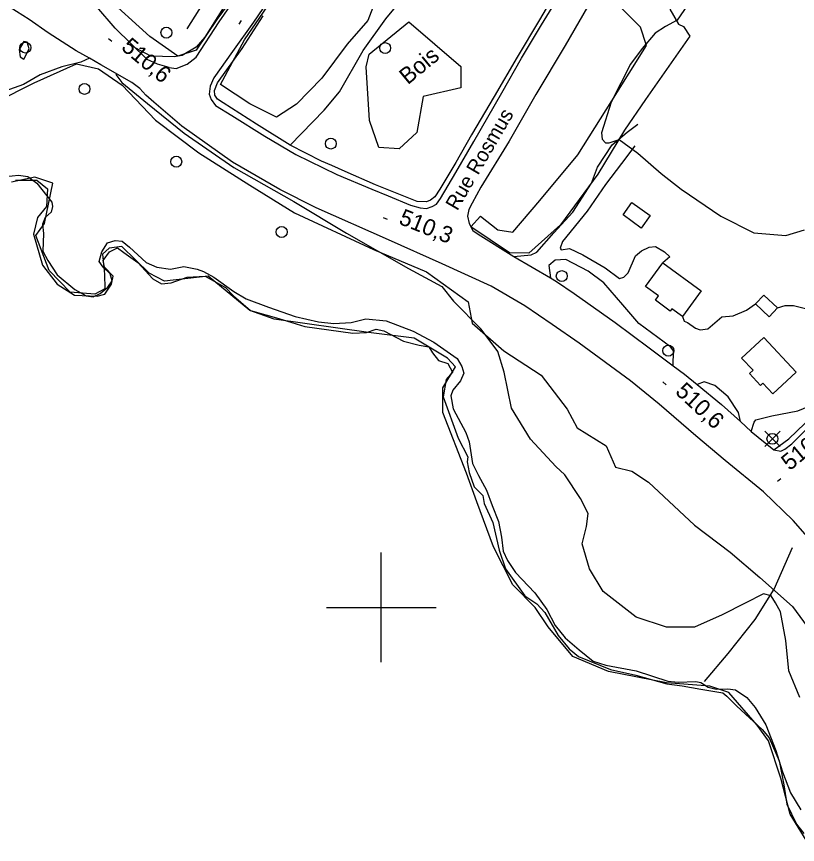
# Model space of a CAD drawing. Extents: x 347059 to 352153, y 6073752 to 6078601.
# Drawn here: x 348500 to 348714.1, y 6075235 to 6075461.9 of the extents above; entities that cross this region are included whole.
import ezdxf

# ---------------------------------------------------------------- set-up
doc = ezdxf.new("R2010")
doc.units = 0
for name, color, linetype in [('Level 1', 7, 'Continuous'), ('Level 19', 7, 'Continuous'), ('Level 2', 7, 'Continuous'), ('Level 21', 7, 'Continuous'), ('Level 22', 7, 'Continuous'), ('Level 3', 7, 'Continuous'), ('Level 31', 7, 'Continuous'), ('Level 36', 7, 'Continuous'), ('Level 4', 7, 'Continuous'), ('Level 44', 7, 'Continuous'), ('Level 61', 7, 'Continuous')]:
    doc.layers.add(name, color=color, linetype=linetype)

msp = doc.modelspace()

# ---------------------------------------------------------------- linework, layer by layer
at = {"layer": 'Level 1'}
for points in [[(348586.89, 6075523.19), (348588.74, 6075526.22), (348589.72, 6075528.31), (348591.57, 6075530.52), (348595.8, 6075537.93), (348597.8, 6075542.22), (348601.17, 6075545.77), (348611.35, 6075553.01), (348622.93, 6075562.08), (348621.01, 6075559.51), (348614.27, 6075550.4), (348605.23, 6075539.9), (348598, 6075529.85), (348588.42, 6075514.02), (348577.01, 6075496.6), (348565.29, 6075478.17), (348558.76, 6075467.65), (348551.57, 6075456.28), (348549.21, 6075453.5), (348545.43, 6075451.26), (348543.17, 6075450.9), (348536.78, 6075451.08), (348532.66, 6075453.22)], [(348527.42, 6075446.27), (348527.22, 6075446.01), (348528.9, 6075443.8), (348535.93, 6075438.06), (348545.95, 6075429.99), (348559.54, 6075420.52), (348576.02, 6075411.19), (348590.44, 6075402.54), (348607.48, 6075392.91), (348616.57, 6075387.96), (348619.81, 6075383.95)], [(348714.74, 6075275.31), (348711.69, 6075282.58), (348711.69, 6075282.58), (348710.87, 6075290.94), (348709.42, 6075298.78), (348708.11, 6075301.22), (348706.88, 6075303.16), (348704.8, 6075303.72), (348699.79, 6075301.14), (348693.41, 6075297.97), (348685.86, 6075294.61), (348678.18, 6075294.61), (348669.87, 6075297.28), (348660.81, 6075304.39), (348657.03, 6075310.57), (348655.05, 6075317.45), (348656.21, 6075322.14), (348656.68, 6075325.73), (348654.6, 6075329.85), (348650.27, 6075336.37), (348647.86, 6075338.64), (348640.86, 6075346.14), (348635.7, 6075354.64), (348633.69, 6075364.43), (348631.9, 6075370.13), (348627.38, 6075376.24), (348619.81, 6075383.95)]]:
    msp.add_lwpolyline(points, dxfattribs=at)
at = {"layer": 'Level 19'}
for points in [[(348501.98, 6075450.24), (348503.48, 6075453.06), (348502.91, 6075454.92), (348502.02, 6075455.08), (348500.67, 6075452.91), (348500.97, 6075450.83), (348501.98, 6075450.24)], [(348519.99, 6075450.5), (348517.58, 6075449.42), (348512.45, 6075448.17), (348506.45, 6075445.97), (348501.92, 6075443.27), (348498.1, 6075441.9), (348493.28, 6075441.36), (348488.71, 6075442.6), (348484.26, 6075443.88), (348476.57, 6075447.79), (348471.59, 6075449.89), (348468.05, 6075450.79), (348463.98, 6075451.17), (348456.84, 6075449.61), (348454.27, 6075450.26)], [(348636.37, 6075396.13), (348641.1, 6075396.6), (348642.61, 6075397.32), (348647.34, 6075402.67), (348652.55, 6075408.27), (348657.58, 6075416.26), (348659.26, 6075420.66), (348663.32, 6075426.73), (348667.39, 6075430.25), (348670.31, 6075432.44)], [(348669.5, 6075426.44), (348665.81, 6075421.66), (348661.45, 6075415.86), (348656.45, 6075408.57), (348649.67, 6075400.25), (348649, 6075398.42), (348649.33, 6075397.94), (348651.63, 6075398.34), (348655.25, 6075396.61), (348661.33, 6075393.01), (348665.34, 6075390.09), (348666.45, 6075390.48), (348667.67, 6075391.72), (348669.71, 6075396.34), (348671.35, 6075397.7), (348673.42, 6075398.74), (348675.2, 6075398.87), (348677.62, 6075397.41), (348679.1, 6075396.08), (348677.18, 6075394.43)], [(348680.05, 6075366.2), (348680.06, 6075370.35), (348679.3, 6075371.44), (348670.6, 6075377.84), (348666.22, 6075382.92), (348660.98, 6075388.95), (348656.75, 6075392.13), (348650.55, 6075395.34), (348647.65, 6075395.11), (348645.91, 6075393.67), (348646.36, 6075390.27)], [(348682.59, 6075379.68), (348683.07, 6075378.46), (348683.92, 6075378.07), (348686.16, 6075376.55), (348687.4, 6075376.07), (348689.48, 6075376.36), (348693.4, 6075379.61), (348696.47, 6075379.91), (348700.16, 6075381.45), (348702.62, 6075383.16)], [(348708.62, 6075382.07), (348710.74, 6075382.77), (348713.04, 6075382.72), (348717.06, 6075381.7), (348721.52, 6075379.23), (348725.3, 6075375.59), (348728.78, 6075371.41), (348732.03, 6075367.33), (348734.32, 6075364.05)], [(348698.43, 6075350.91), (348697.93, 6075353.43), (348695.07, 6075357.68), (348691.41, 6075360.81), (348688.54, 6075361.81), (348686.59, 6075361.05)], [(348701.43, 6075348.24), (348702.24, 6075350.79), (348702.71, 6075351.41), (348707.09, 6075352.48), (348714.22, 6075353.87), (348717.26, 6075355.11), (348721.81, 6075355.53)]]:
    msp.add_lwpolyline(points, dxfattribs=at)
at = {"layer": 'Level 2'}
for points in [[(348718.72, 6075506.29), (348718.55, 6075505.87), (348712.32, 6075499.96), (348709.01, 6075498.34), (348705.59, 6075496.93), (348701.92, 6075494.19), (348699.25, 6075491.97), (348696.35, 6075487.77), (348688.71, 6075477.68), (348686.13, 6075471.65), (348684.8, 6075466.19), (348681.14, 6075460.91), (348677.9, 6075459.2)], [(348677.9, 6075459.2), (348675.09, 6075457.32), (348671.5, 6075453.14), (348668.35, 6075448.88), (348663.06, 6075438.41), (348660.39, 6075430.04), (348660.51, 6075428.27), (348661.45, 6075427.32), (348662.51, 6075427.3), (348665.23, 6075428.2), (348670.35, 6075424.49), (348676.69, 6075418.86), (348682.21, 6075414.57), (348693.08, 6075407.21), (348702.12, 6075402.68), (348710.94, 6075401.94), (348716.01, 6075403.44)], [(348495.23, 6075417.92), (348500.54, 6075418.43), (348503.06, 6075418.12)], [(348503.06, 6075418.12), (348505.52, 6075416.28), (348509.71, 6075411.06), (348509.89, 6075409.87), (348509.46, 6075408.31), (348507.86, 6075406.85), (348507.11, 6075405.03), (348507.38, 6075402.44), (348507.23, 6075397.64), (348508.6, 6075395.03), (348511.16, 6075391.13), (348515.96, 6075387.1), (348519.09, 6075385.41), (348521.04, 6075385.15), (348522.95, 6075386.06), (348525, 6075387.76), (348526.25, 6075389.47), (348525.7, 6075391.42), (348523.76, 6075393.28), (348522.65, 6075394.78), (348523.34, 6075397.48), (348524.95, 6075399.89), (348527.05, 6075400.56), (348528.93, 6075400.38), (348530.97, 6075398.72), (348535.54, 6075394.49), (348538.41, 6075393.27), (348542.22, 6075392.68), (348545.86, 6075393.43), (348549.51, 6075392.72), (348551.27, 6075392.04), (348554.04, 6075390.46), (348559.52, 6075386.58), (348562.9, 6075384.58), (348569.1, 6075382.23), (348576.36, 6075379.72), (348582.78, 6075378.23), (348586.97, 6075377.83), (348591.72, 6075378.03), (348595.75, 6075379.1), (348601.29, 6075378.5), (348608.75, 6075375.74), (348614.36, 6075372.66), (348620.79, 6075368.25), (348622.11, 6075366.01), (348622.59, 6075364.15), (348621.75, 6075362.11), (348619.63, 6075359.55), (348619.05, 6075358), (348619.74, 6075354.43), (348623.14, 6075347.92), (348624.06, 6075345.35), (348624.97, 6075339.43), (348626.63, 6075336.14), (348628.88, 6075332.14), (348630.38, 6075327.92), (348632.16, 6075323.52), (348632.93, 6075319.22), (348633.44, 6075315.38), (348634.59, 6075312.87), (348636.83, 6075309.53), (348642.06, 6075304.01), (348645.42, 6075299.46), (348647.63, 6075295.03), (348650.44, 6075291.63)], [(348650.44, 6075291.63), (348654.21, 6075288.36), (348658.07, 6075285.3), (348661.52, 6075284.18), (348669.87, 6075282.59), (348678.54, 6075279.81), (348681.42, 6075279.54), (348686.22, 6075279.67), (348687.63, 6075279.38), (348689.6, 6075278.16), (348691.76, 6075277.61), (348695.03, 6075277.67), (348697.11, 6075277.4), (348700.18, 6075275.29), (348702.47, 6075272.53), (348705.44, 6075267.81), (348708.2, 6075260.78), (348709.98, 6075254.94), (348712.21, 6075249.2), (348715.04, 6075244.5)]]:
    msp.add_lwpolyline(points, dxfattribs=at)
at = {"layer": 'Level 21'}
for points in [[(348601.9, 6075412.8), (348608.04, 6075410.22), (348610.65, 6075409.53), (348612.35, 6075409.29), (348613.97, 6075409.88), (348615.14, 6075410.47), (348616.23, 6075412.05), (348620.39, 6075419.18), (348625.38, 6075427.67), (348633.04, 6075441.01), (348638.45, 6075450.53), (348643.95, 6075459.67), (348651.96, 6075472.77)], [(348541.79, 6075447.93), (348543.74, 6075447.67), (348546.81, 6075448.87), (348549.25, 6075450.74), (348555.5, 6075460.42), (348561.36, 6075468.96)], [(348657.9, 6075467.03), (348650.44, 6075454), (348642.35, 6075440.54), (348635.04, 6075427.79), (348627.32, 6075415.16), (348624.93, 6075410.78), (348623.95, 6075409.07), (348623.66, 6075407.25), (348624.08, 6075405.19), (348625.06, 6075403.3), (348626.57, 6075402.3), (348636.37, 6075396.13), (348646.36, 6075390.27), (348647.99, 6075389.3), (348652.83, 6075386.02), (348664.11, 6075378.08), (348673.42, 6075371.13), (348680.05, 6075366.2), (348683.12, 6075363.91), (348686.59, 6075361.05), (348693.22, 6075355.57), (348698.43, 6075350.91), (348701.43, 6075348.24), (348707.59, 6075343.19), (348709.49, 6075342.81), (348710.66, 6075343.4), (348712.56, 6075344.82), (348720.13, 6075352.3)], [(348535.41, 6075440.39), (348533.79, 6075442.15), (348531.61, 6075443.88), (348523.14, 6075448.72), (348519.99, 6075450.5), (348516.35, 6075452.55), (348508.63, 6075457.49), (348503.43, 6075461.13), (348498.22, 6075464.4)], [(348541.79, 6075447.93), (348538.63, 6075448.84), (348535.83, 6075450.13), (348527.01, 6075458.74), (348521.98, 6075464.56)], [(348568.84, 6075466.13), (348564.93, 6075460.33), (348559.16, 6075452.33), (348554.05, 6075445.08), (348553.09, 6075442.79), (348552.77, 6075440.64), (348553.33, 6075439.15), (348554.5, 6075437.56), (348558.97, 6075434.81), (348568.02, 6075429.17), (348576.6, 6075424.11), (348587.81, 6075418.59), (348597.43, 6075414.62), (348601.9, 6075412.8)], [(348722.14, 6075313.27), (348712.94, 6075323.79), (348704.81, 6075331.65), (348694.28, 6075340.23), (348686.23, 6075347.02), (348676.16, 6075355.68), (348668.28, 6075362.09), (348654.25, 6075372.43), (348646.83, 6075377.55), (348639.36, 6075382.64), (348630.07, 6075388.02), (348616.69, 6075394.15), (348602, 6075400.76), (348582.17, 6075409.5), (348572.22, 6075414.49), (348559.23, 6075422.05), (348545.3, 6075431.84), (348537.61, 6075438.46), (348535.41, 6075440.39)]]:
    msp.add_lwpolyline(points, dxfattribs=at)
at = {"layer": 'Level 22'}
for points in [[(348574.97, 6075426.71), (348584.34, 6075436.28), (348588.51, 6075441.31), (348595.02, 6075452.57), (348601.26, 6075461.27), (348605.29, 6075466.11), (348608.57, 6075471.76), (348613.69, 6075486.97), (348618.83, 6075495.28), (348627.44, 6075507.37), (348638.42, 6075522.78), (348642.66, 6075527.73), (348650.28, 6075534.42), (348657.91, 6075540.82), (348668.12, 6075548.99), (348679.06, 6075557.38), (348686.99, 6075564.77), (348691.64, 6075569.23), (348695.59, 6075571.53), (348704.1, 6075575.43), (348714.18, 6075580.41), (348727.56, 6075583.17), (348738.27, 6075584.32), (348743.55, 6075585.93)], [(348650.14, 6075472.57), (348643.39, 6075461.04), (348637.21, 6075450.82), (348630.93, 6075439.98), (348624.69, 6075429.47), (348620.41, 6075421.94), (348616.02, 6075414.63), (348614.71, 6075412.49), (348613.44, 6075411.58), (348612.37, 6075411.15), (348609.79, 6075411.26), (348598.36, 6075415.77), (348590.06, 6075419.41)], [(348590.06, 6075419.41), (348586.41, 6075421.1), (348583.56, 6075422.27), (348574.97, 6075426.71), (348565.76, 6075432.45), (348556.64, 6075438.26), (348555.05, 6075439.27), (348554.34, 6075440.4), (348554.29, 6075441.64), (348555.06, 6075443.79), (348561.86, 6075453.18), (348567.63, 6075462.09)], [(348707.59, 6075343.19), (348711.76, 6075346.2), (348716.1, 6075350.35), (348721.81, 6075355.53), (348727.43, 6075359.74), (348733.77, 6075363.71), (348734.32, 6075364.05), (348741.33, 6075368.39), (348751.25, 6075374.58), (348758.79, 6075379.02), (348762.93, 6075381.47)], [(348688.63, 6075279.73), (348695.12, 6075287.36), (348702.5, 6075296.64), (348707.73, 6075305.04), (348712.7, 6075316.46)]]:
    msp.add_lwpolyline(points, dxfattribs=at)
at = {"layer": 'Level 3'}
for p, q in [((348561, 6075459.84), (348561.64, 6075460.86)), ((348525.16, 6075455.91), (348526.08, 6075455.14)), ((348600.51, 6075406.85), (348601.63, 6075406.4)), ((348677.2, 6075361.78), (348678.08, 6075360.96)), ((348708.62, 6075334.58), (348709.54, 6075335.35))]:
    msp.add_line(p, q, dxfattribs=at)
at = {"layer": 'Level 31'}
for points in [[(348666.26, 6075407.53), (348668.71, 6075410.98), (348673.74, 6075407.42), (348671.28, 6075403.96), (348666.26, 6075407.53)], [(348677.18, 6075394.43), (348687.73, 6075386.71), (348682.59, 6075379.68), (348679.64, 6075381.84), (348679.19, 6075381.22), (348675.15, 6075384.18), (348676.01, 6075385.36), (348672.45, 6075387.97), (348677.18, 6075394.43)], [(348704.88, 6075385.57), (348708.62, 6075382.07), (348706.36, 6075379.66), (348702.62, 6075383.16), (348704.88, 6075385.57)], [(348704.85, 6075373.99), (348713.73, 6075364.49), (348707.35, 6075358.53), (348704.61, 6075361.46), (348703.93, 6075360.83), (348700.91, 6075364.07), (348701.9, 6075365), (348698.79, 6075368.33), (348704.85, 6075373.99)]]:
    msp.add_lwpolyline(points, dxfattribs=at)
at = {"layer": 'Level 36'}
for p, q in [((348709.33, 6075344.07), (348705.1, 6075348.3)), ((348705.1, 6075344.07), (348709.33, 6075348.3))]:
    msp.add_line(p, q, dxfattribs=at)
for centre in [(348541.08, 6075457.5), (348502.41, 6075453.41), (348601.05, 6075453.27), (348518.62, 6075442.08), (348586.15, 6075427.1), (348543.77, 6075422.14), (348572.67, 6075402.88), (348649.48, 6075390.8), (348678.68, 6075370.36), (348707.22, 6075346.19)]:
    msp.add_circle(centre, 1.5, dxfattribs=at)
at = {"layer": 'Level 4'}
for points in [[(348546.75, 6075458.56), (348553.32, 6075469.05), (348561.6, 6075479.29), (348572.87, 6075494.65), (348579.29, 6075505.23), (348587.72, 6075517.56), (348592.34, 6075526.37), (348593.08, 6075527.79), (348600.5, 6075537.62), (348606.16, 6075544.94)], [(348499.69, 6075417.03), (348505.54, 6075417.07), (348508.49, 6075414.7), (348508.21, 6075409.87), (348505.74, 6075406.85), (348504.62, 6075402.3), (348507.07, 6075393.81), (348511.12, 6075388.58), (348515.86, 6075385.59), (348522.14, 6075385.29), (348524.16, 6075385.84), (348525.98, 6075388.56), (348526.48, 6075390.77), (348524.07, 6075393.22), (348523.75, 6075395.06), (348525.46, 6075397.45), (348527.66, 6075398.52), (348529.43, 6075397.21), (348533.21, 6075394.47), (348537.33, 6075390.06), (348539.71, 6075388.64), (348542.38, 6075388.97), (348546.81, 6075390.54), (348551.69, 6075390.74), (348557.26, 6075387.68), (348559.43, 6075385.34), (348564.13, 6075381.4), (348571.87, 6075379.16), (348579.05, 6075376.97)], [(348579.05, 6075376.97), (348592.19, 6075375.14), (348595.96, 6075375.32), (348598.56, 6075376.28), (348600.67, 6075375.83), (348606.09, 6075372.94), (348610.4, 6075371.85), (348612.99, 6075371.36), (348614.03, 6075369.74), (348615.66, 6075367.69), (348618.21, 6075366.8), (348619.48, 6075364.46), (348617.81, 6075362.47), (348616.95, 6075357.69), (348621.09, 6075346.35), (348623.71, 6075341.29), (348623.54, 6075339.87), (348624.1, 6075337.01), (348625.42, 6075333.06), (348627.79, 6075330.66), (348628.21, 6075328.44), (348630.53, 6075323.28), (348632.3, 6075315.7), (348634.01, 6075310.56), (348639.34, 6075303.14), (348642.6, 6075300.94), (348644.86, 6075298.59), (348648.52, 6075292.28), (348651.48, 6075288.62), (348654.09, 6075286.56), (348662.84, 6075282.95), (348669.75, 6075281.44), (348678.28, 6075279.08), (348682.52, 6075278.52), (348687.56, 6075277.64), (348693.66, 6075276.57), (348694.69, 6075275.69), (348697.44, 6075272.92), (348704.44, 6075266.5), (348706.3, 6075264.27), (348709.06, 6075257.95), (348710.31, 6075251.36), (348711.17, 6075246.05), (348713.84, 6075240.56), (348715.84, 6075238.06)]]:
    msp.add_lwpolyline(points, dxfattribs=at)
at = {"layer": 'Level 44'}
for points in [[(348583.72, 6075445.01), (348576.72, 6075437.86), (348571.22, 6075434.35), (348563.99, 6075437.97), (348555.94, 6075443.31), (348562.51, 6075455.51), (348567.66, 6075463.08), (348578.56, 6075479.47), (348589.72, 6075495.93), (348600.07, 6075512.62), (348602.96, 6075514.57), (348615.81, 6075506), (348618.95, 6075500.79), (348606.98, 6075494.18), (348605.33, 6075490.55), (348597.71, 6075464.42), (348596.31, 6075460.86), (348590.6, 6075454.33), (348583.72, 6075445.01)], [(348569.41, 6075480.8), (348554.91, 6075461.12), (348549.28, 6075452.7), (348544.19, 6075451.03), (348536.56, 6075456.42), (348523.84, 6075468.09)], [(348659.33, 6075418.68), (348649.16, 6075404.85), (348640.46, 6075397.04), (348635.12, 6075397.12), (348624.52, 6075404.26), (348627.18, 6075407.21), (348631.93, 6075403.49), (348636.07, 6075402.86), (348643.46, 6075411.54), (348653.83, 6075424.04), (348663.18, 6075438.85), (348672.73, 6075453.96), (348671.06, 6075459.03), (348660.47, 6075469.76)], [(348679.1, 6075463.91), (348681.51, 6075459.8), (348682.83, 6075459.18), (348684.56, 6075456.56), (348672.43, 6075439.16), (348666.64, 6075430.76), (348659.33, 6075418.68)], [(348621.82, 6075442.39), (348611.48, 6075439.98), (348609.74, 6075430.13), (348604.89, 6075425.65), (348599.33, 6075426), (348596.74, 6075433.46), (348595.81, 6075448.15), (348596.7, 6075451.6), (348607.56, 6075460.44), (348621.79, 6075448.22), (348621.82, 6075442.39)], [(348494.37, 6075438.55), (348504.8, 6075443.74), (348516.46, 6075448.91), (348522.42, 6075447.54)], [(348522.42, 6075447.54), (348528.98, 6075443.07), (348538.12, 6075433.53), (348549.94, 6075424.55), (348563.92, 6075415.71), (348576.21, 6075408.16), (348597.81, 6075398.11), (348612.38, 6075392), (348623.79, 6075383.72), (348624.89, 6075377.87), (348633.56, 6075370.32), (348643.8, 6075363.63), (348650.92, 6075354.34), (348653.65, 6075349.24), (348661.67, 6075344.31), (348664.16, 6075338.41), (348668.67, 6075337.33), (348673.25, 6075334.36), (348685.82, 6075322.51), (348695.67, 6075315.18), (348703.75, 6075308.18), (348712.74, 6075300.28), (348726.77, 6075281.04)], [(348717.2, 6075235.04), (348712.12, 6075243.35), (348709.49, 6075253.23), (348706.14, 6075263.43), (348703, 6075267.76), (348695.25, 6075276.72), (348690.05, 6075278.44), (348678.17, 6075279.3), (348662.29, 6075282.42), (348652.53, 6075286.54), (348645.78, 6075294.66), (348642.15, 6075299.94), (348636.06, 6075306.19), (348630.76, 6075316.56), (348626.22, 6075328.91), (348623.33, 6075336.75), (348616.88, 6075353.4), (348616.85, 6075360.15), (348620.36, 6075365.91), (348618.1, 6075368.26), (348608.98, 6075373.8), (348596.52, 6075375.36), (348570.58, 6075379), (348563.96, 6075381.34), (348552.49, 6075390.79), (348540.51, 6075389.43), (348536.34, 6075391.55), (348528.88, 6075398.9), (348525.37, 6075398.4), (348523.57, 6075396.76), (348524.14, 6075391.36), (348524.17, 6075387.33), (348521.48, 6075385.85), (348514.7, 6075386.4), (348508.91, 6075392.28), (348505.28, 6075401.91), (348507.65, 6075405.22), (348509.92, 6075416.28), (348504.97, 6075417.89), (348498.58, 6075416.5)]]:
    msp.add_lwpolyline(points, dxfattribs=at)
at = {"layer": 'Level 61'}
for p, q in [((348600, 6075285), (348600, 6075315)), ((348585, 6075300), (348615, 6075300))]:
    msp.add_line(p, q, dxfattribs=at)

# ---------------------------------------------------------------- texts
at = {"layer": 'Level 21'}
msp.add_text('Rue Rosmus', height=4, rotation=59.7118, dxfattribs=at).set_placement((348620.81, 6075408.5))
at = {"layer": 'Level 3'}
for s, rotation, p in [('510,6', 319.9409, (348528.44, 6075453.08)), ('510,3', 338.1676, (348604.51, 6075405.19)), ('510,6', 317.1395, (348680.34, 6075358.8)), ('510,6', 39.62, (348711.98, 6075337.3))]:
    msp.add_text(s, height=4.5, rotation=rotation, dxfattribs=at).set_placement(p)
at = {"layer": 'Level 44'}
msp.add_text('Bois', height=4.5, rotation=39.568, dxfattribs=at).set_placement((348607.25, 6075443.07))

doc.saveas('drawing.dxf')
